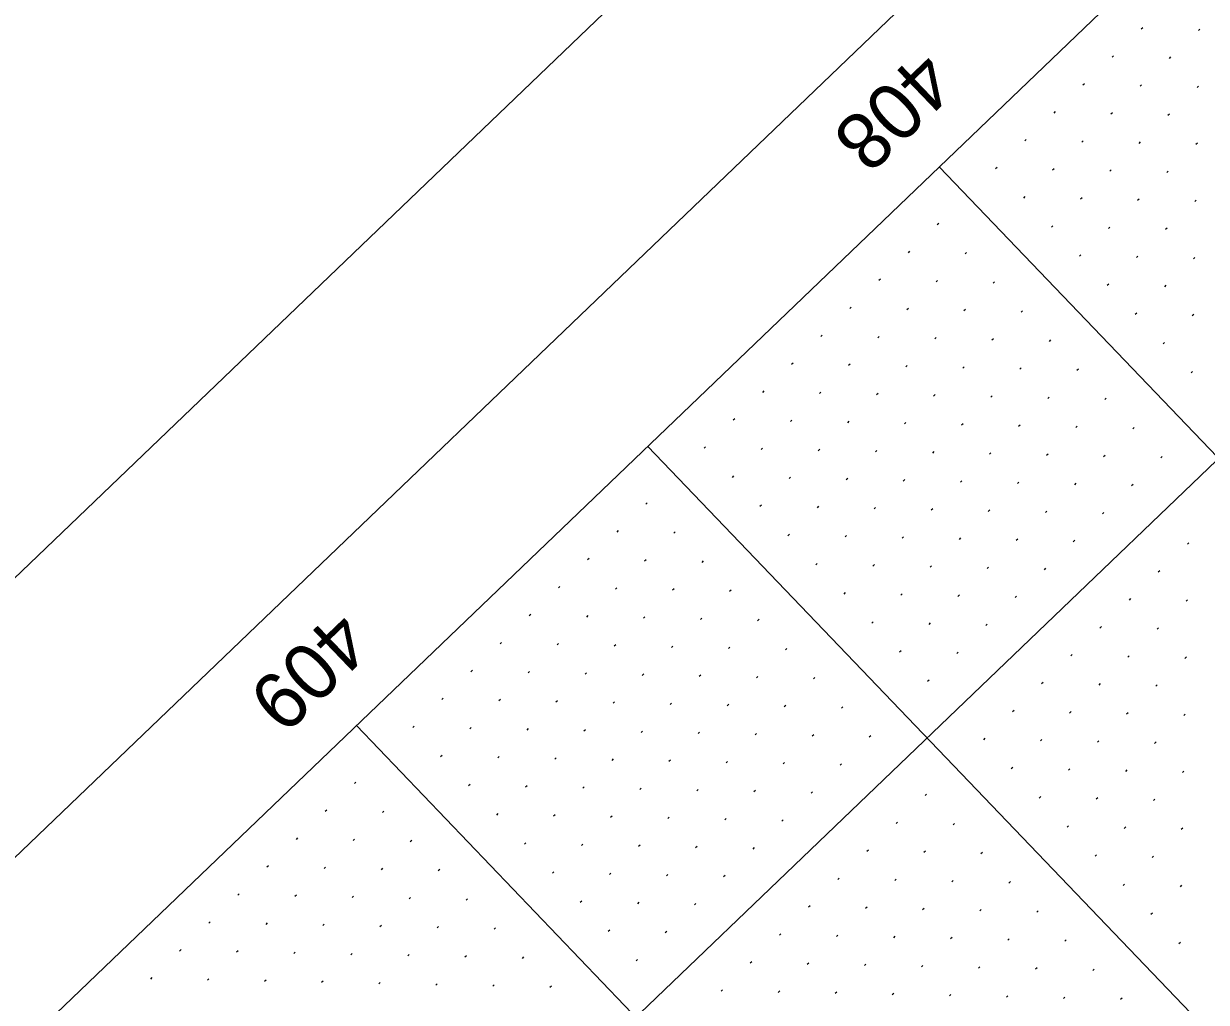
# Model space of a CAD drawing. Extents: x 2148987 to 2151117, y 142806 to 144993.
# Drawn here: x 2149870.3 to 2150016.8, y 144383.4 to 144504.6 of the extents above; entities that cross this region are included whole.
import ezdxf

# ---------------------------------------------------------------- set-up
doc = ezdxf.new("R2010")
doc.units = 0
for name, color, linetype in [('BASELINE', 7, 'Continuous'), ('PR_PIER_PH3', 7, 'Continuous'), ('PR_Road_Concrete', 7, 'Continuous'), ('SHT_Profile_Grid_Minor', 7, 'Continuous'), ('Wall D Bore Txt', 7, 'Continuous')]:
    doc.layers.add(name, color=color, linetype=linetype)

msp = doc.modelspace()

# ---------------------------------------------------------------- linework, layer by layer
at = {"layer": 'BASELINE'}
msp.add_lwpolyline([(2151029.45, 144024.32), (2149802.07, 142848.08), (2149040.98, 143642.27), (2150268.36, 144818.51)], close=True, dxfattribs=at)
at = {"layer": 'PR_PIER_PH3'}
for p, q in [((2150261.97, 144684.26), (2149124.83, 143594.52)), ((2149983.7, 144486.85), (2150329.49, 144126.02)), ((2149947.6, 144452.25), (2150293.55, 144091.26)), ((2149911.5, 144417.66), (2150233.24, 144081.93))]:
    msp.add_line(p, q, dxfattribs=at)
at = {"layer": 'PR_Road_Concrete'}
msp.add_line((2150227.37, 144720.36), (2149279.76, 143812.24), dxfattribs=at)
msp.add_lwpolyline([(2150941.76, 143974.91), (2149804.63, 142885.16), (2149078.13, 143643.25), (2150215.26, 144733)], close=True, dxfattribs=at)
at = {"layer": 'SHT_Profile_Grid_Minor'}
for p, q in [((2150008.91, 144504.08), (2150008.73, 144503.91)), ((2150015.98, 144503.93), (2150015.8, 144503.76)), ((2150005.3, 144500.62), (2150005.12, 144500.45)), ((2150012.37, 144500.47), (2150012.19, 144500.3)), ((2150001.69, 144497.16), (2150001.51, 144496.99)), ((2150008.76, 144497.01), (2150008.58, 144496.84)), ((2150015.83, 144496.86), (2150015.65, 144496.69)), ((2149998.08, 144493.7), (2149997.9, 144493.53)), ((2150005.15, 144493.55), (2150004.97, 144493.38)), ((2150012.22, 144493.4), (2150012.04, 144493.23)), ((2149994.47, 144490.24), (2149994.29, 144490.07)), ((2150001.54, 144490.09), (2150001.36, 144489.92)), ((2150008.61, 144489.94), (2150008.43, 144489.77)), ((2150015.68, 144489.79), (2150015.5, 144489.62)), ((2149990.86, 144486.78), (2149990.68, 144486.61)), ((2149997.93, 144486.63), (2149997.75, 144486.46)), ((2150005, 144486.48), (2150004.82, 144486.31)), ((2150012.07, 144486.33), (2150011.89, 144486.16)), ((2149994.32, 144483.17), (2149994.14, 144483)), ((2150001.39, 144483.02), (2150001.21, 144482.85)), ((2150008.46, 144482.87), (2150008.28, 144482.7)), ((2150015.53, 144482.72), (2150015.35, 144482.55)), ((2149983.64, 144479.86), (2149983.46, 144479.69)), ((2149997.78, 144479.56), (2149997.6, 144479.39)), ((2150004.85, 144479.41), (2150004.67, 144479.24)), ((2150011.92, 144479.26), (2150011.74, 144479.09)), ((2149980.03, 144476.4), (2149979.85, 144476.23)), ((2149987.1, 144476.25), (2149986.92, 144476.08)), ((2150001.24, 144475.95), (2150001.06, 144475.78)), ((2150008.31, 144475.8), (2150008.13, 144475.63)), ((2150015.38, 144475.65), (2150015.2, 144475.48)), ((2149976.42, 144472.94), (2149976.24, 144472.77)), ((2149983.49, 144472.79), (2149983.31, 144472.62)), ((2149990.56, 144472.64), (2149990.38, 144472.47)), ((2150004.7, 144472.34), (2150004.52, 144472.17)), ((2150011.77, 144472.19), (2150011.59, 144472.02)), ((2149972.81, 144469.48), (2149972.63, 144469.31)), ((2149979.88, 144469.33), (2149979.7, 144469.16)), ((2149986.95, 144469.18), (2149986.77, 144469.01)), ((2149994.02, 144469.03), (2149993.84, 144468.86)), ((2150008.16, 144468.73), (2150007.98, 144468.56)), ((2150015.23, 144468.58), (2150015.05, 144468.41)), ((2149969.2, 144466.03), (2149969.02, 144465.85)), ((2149976.27, 144465.87), (2149976.09, 144465.7)), ((2149983.34, 144465.72), (2149983.16, 144465.55)), ((2149990.41, 144465.57), (2149990.23, 144465.4)), ((2149997.48, 144465.42), (2149997.3, 144465.25)), ((2150011.62, 144465.12), (2150011.44, 144464.95)), ((2149965.59, 144462.57), (2149965.41, 144462.39)), ((2149972.66, 144462.42), (2149972.48, 144462.24)), ((2149979.73, 144462.27), (2149979.55, 144462.09)), ((2149986.8, 144462.11), (2149986.62, 144461.94)), ((2149993.87, 144461.96), (2149993.69, 144461.79)), ((2150000.94, 144461.81), (2150000.76, 144461.64)), ((2150015.08, 144461.51), (2150014.9, 144461.34)), ((2149961.98, 144459.11), (2149961.8, 144458.93)), ((2149969.05, 144458.96), (2149968.87, 144458.78)), ((2149976.12, 144458.81), (2149975.94, 144458.63)), ((2149983.19, 144458.66), (2149983.01, 144458.48)), ((2149990.26, 144458.5), (2149990.08, 144458.33)), ((2149997.33, 144458.35), (2149997.15, 144458.18)), ((2150004.4, 144458.2), (2150004.22, 144458.03)), ((2149958.37, 144455.65), (2149958.19, 144455.47)), ((2149965.44, 144455.5), (2149965.26, 144455.32)), ((2149972.51, 144455.35), (2149972.33, 144455.17)), ((2149979.58, 144455.2), (2149979.4, 144455.02)), ((2149986.65, 144455.05), (2149986.47, 144454.87)), ((2149993.72, 144454.89), (2149993.54, 144454.72)), ((2150000.79, 144454.74), (2150000.61, 144454.57)), ((2150007.86, 144454.59), (2150007.68, 144454.42)), ((2149954.76, 144452.19), (2149954.58, 144452.01)), ((2149961.83, 144452.04), (2149961.65, 144451.86)), ((2149968.9, 144451.89), (2149968.72, 144451.71)), ((2149975.97, 144451.74), (2149975.79, 144451.56)), ((2149983.04, 144451.59), (2149982.86, 144451.41)), ((2149990.11, 144451.44), (2149989.93, 144451.26)), ((2149997.18, 144451.28), (2149997, 144451.11)), ((2150004.25, 144451.13), (2150004.07, 144450.96)), ((2150011.32, 144450.98), (2150011.14, 144450.81)), ((2149958.22, 144448.58), (2149958.04, 144448.4)), ((2149965.29, 144448.43), (2149965.11, 144448.25)), ((2149972.36, 144448.28), (2149972.18, 144448.1)), ((2149979.43, 144448.13), (2149979.25, 144447.95)), ((2149986.5, 144447.98), (2149986.32, 144447.8)), ((2149993.57, 144447.83), (2149993.39, 144447.65)), ((2150000.64, 144447.67), (2150000.46, 144447.5)), ((2150007.71, 144447.52), (2150007.53, 144447.35)), ((2149947.54, 144445.27), (2149947.36, 144445.1)), ((2149961.68, 144444.97), (2149961.5, 144444.79)), ((2149968.75, 144444.82), (2149968.57, 144444.64)), ((2149975.82, 144444.67), (2149975.64, 144444.49)), ((2149982.89, 144444.52), (2149982.71, 144444.34)), ((2149989.96, 144444.37), (2149989.78, 144444.19)), ((2149997.03, 144444.22), (2149996.85, 144444.04)), ((2150004.1, 144444.06), (2150003.92, 144443.89)), ((2149943.93, 144441.81), (2149943.75, 144441.64)), ((2149951, 144441.66), (2149950.82, 144441.49)), ((2149965.14, 144441.36), (2149964.96, 144441.18)), ((2149972.21, 144441.21), (2149972.03, 144441.03)), ((2149979.28, 144441.06), (2149979.1, 144440.88)), ((2149986.35, 144440.91), (2149986.17, 144440.73)), ((2149993.42, 144440.76), (2149993.24, 144440.58)), ((2150000.49, 144440.61), (2150000.31, 144440.43)), ((2150014.63, 144440.3), (2150014.44, 144440.13)), ((2149940.32, 144438.35), (2149940.14, 144438.18)), ((2149947.39, 144438.2), (2149947.21, 144438.03)), ((2149954.46, 144438.05), (2149954.28, 144437.88)), ((2149968.6, 144437.75), (2149968.42, 144437.57)), ((2149975.67, 144437.6), (2149975.49, 144437.42)), ((2149982.74, 144437.45), (2149982.56, 144437.27)), ((2149989.81, 144437.3), (2149989.63, 144437.12)), ((2149996.88, 144437.15), (2149996.7, 144436.97)), ((2150011.02, 144436.84), (2150010.83, 144436.67)), ((2149936.71, 144434.89), (2149936.53, 144434.72)), ((2149943.78, 144434.74), (2149943.6, 144434.57)), ((2149950.85, 144434.59), (2149950.67, 144434.42)), ((2149957.92, 144434.44), (2149957.74, 144434.27)), ((2149972.06, 144434.14), (2149971.88, 144433.96)), ((2149979.13, 144433.99), (2149978.95, 144433.81)), ((2149986.2, 144433.84), (2149986.02, 144433.66)), ((2149993.27, 144433.69), (2149993.09, 144433.51)), ((2150007.41, 144433.39), (2150007.22, 144433.21)), ((2150014.47, 144433.23), (2150014.29, 144433.06)), ((2149933.1, 144431.43), (2149932.92, 144431.26)), ((2149940.17, 144431.28), (2149939.99, 144431.11)), ((2149947.24, 144431.13), (2149947.06, 144430.96)), ((2149954.31, 144430.98), (2149954.13, 144430.81)), ((2149961.38, 144430.83), (2149961.2, 144430.66)), ((2149975.52, 144430.53), (2149975.34, 144430.35)), ((2149982.59, 144430.38), (2149982.41, 144430.2)), ((2149989.66, 144430.23), (2149989.48, 144430.05)), ((2150003.8, 144429.93), (2150003.61, 144429.75)), ((2150010.86, 144429.78), (2150010.68, 144429.6)), ((2149929.49, 144427.97), (2149929.31, 144427.8)), ((2149936.56, 144427.82), (2149936.38, 144427.65)), ((2149943.63, 144427.67), (2149943.45, 144427.5)), ((2149950.7, 144427.52), (2149950.52, 144427.35)), ((2149957.77, 144427.37), (2149957.59, 144427.2)), ((2149964.84, 144427.22), (2149964.66, 144427.05)), ((2149978.98, 144426.92), (2149978.8, 144426.74)), ((2149986.05, 144426.77), (2149985.87, 144426.59)), ((2150000.19, 144426.47), (2150000, 144426.29)), ((2150007.25, 144426.32), (2150007.07, 144426.14)), ((2150014.32, 144426.17), (2150014.14, 144425.99)), ((2149925.88, 144424.51), (2149925.7, 144424.34)), ((2149932.95, 144424.36), (2149932.77, 144424.19)), ((2149940.02, 144424.21), (2149939.84, 144424.04)), ((2149947.09, 144424.06), (2149946.91, 144423.89)), ((2149954.16, 144423.91), (2149953.98, 144423.74)), ((2149961.23, 144423.76), (2149961.05, 144423.59)), ((2149968.3, 144423.61), (2149968.12, 144423.44)), ((2149982.44, 144423.31), (2149982.26, 144423.13)), ((2149996.58, 144423.01), (2149996.39, 144422.83)), ((2150003.64, 144422.86), (2150003.46, 144422.68)), ((2150010.71, 144422.71), (2150010.53, 144422.53)), ((2149922.27, 144421.05), (2149922.09, 144420.88)), ((2149929.34, 144420.9), (2149929.16, 144420.73)), ((2149936.41, 144420.75), (2149936.23, 144420.58)), ((2149943.48, 144420.6), (2149943.3, 144420.43)), ((2149950.55, 144420.45), (2149950.37, 144420.28)), ((2149957.62, 144420.3), (2149957.44, 144420.13)), ((2149964.69, 144420.15), (2149964.51, 144419.98)), ((2149971.76, 144420), (2149971.58, 144419.83)), ((2149992.97, 144419.55), (2149992.79, 144419.37)), ((2150000.03, 144419.4), (2149999.85, 144419.22)), ((2150007.1, 144419.25), (2150006.92, 144419.07)), ((2150014.17, 144419.1), (2150013.99, 144418.92)), ((2149918.66, 144417.59), (2149918.48, 144417.42)), ((2149925.73, 144417.44), (2149925.55, 144417.27)), ((2149932.8, 144417.29), (2149932.62, 144417.12)), ((2149939.87, 144417.14), (2149939.69, 144416.97)), ((2149946.94, 144416.99), (2149946.76, 144416.82)), ((2149954.01, 144416.84), (2149953.83, 144416.67)), ((2149961.08, 144416.69), (2149960.9, 144416.52)), ((2149968.15, 144416.54), (2149967.97, 144416.37)), ((2149975.22, 144416.39), (2149975.04, 144416.22)), ((2149989.36, 144416.09), (2149989.18, 144415.91)), ((2149996.43, 144415.94), (2149996.24, 144415.76)), ((2150003.49, 144415.79), (2150003.31, 144415.61)), ((2150010.56, 144415.64), (2150010.38, 144415.46)), ((2149922.12, 144413.98), (2149921.94, 144413.81)), ((2149929.19, 144413.83), (2149929.01, 144413.66)), ((2149936.26, 144413.68), (2149936.08, 144413.51)), ((2149943.33, 144413.53), (2149943.15, 144413.36)), ((2149950.4, 144413.38), (2149950.22, 144413.21)), ((2149957.47, 144413.23), (2149957.29, 144413.06)), ((2149964.54, 144413.08), (2149964.36, 144412.91)), ((2149971.61, 144412.93), (2149971.43, 144412.76)), ((2149992.82, 144412.48), (2149992.63, 144412.3)), ((2149999.88, 144412.33), (2149999.7, 144412.15)), ((2150006.95, 144412.18), (2150006.77, 144412)), ((2149911.44, 144410.67), (2149911.26, 144410.5)), ((2150014.02, 144412.03), (2150013.84, 144411.85)), ((2149925.58, 144410.37), (2149925.4, 144410.2)), ((2149932.65, 144410.22), (2149932.47, 144410.05)), ((2149939.72, 144410.07), (2149939.54, 144409.9)), ((2149946.79, 144409.92), (2149946.61, 144409.75)), ((2149953.86, 144409.77), (2149953.68, 144409.6)), ((2149960.93, 144409.62), (2149960.75, 144409.45)), ((2149968, 144409.47), (2149967.82, 144409.3)), ((2149982.14, 144409.17), (2149981.96, 144409)), ((2149996.27, 144408.87), (2149996.09, 144408.69)), ((2150003.34, 144408.72), (2150003.16, 144408.54)), ((2150010.41, 144408.57), (2150010.23, 144408.39)), ((2149907.83, 144407.21), (2149907.65, 144407.04)), ((2149914.9, 144407.06), (2149914.72, 144406.89)), ((2149929.04, 144406.76), (2149928.86, 144406.59)), ((2149936.11, 144406.61), (2149935.93, 144406.44)), ((2149943.18, 144406.46), (2149943, 144406.29)), ((2149950.25, 144406.31), (2149950.07, 144406.14)), ((2149957.32, 144406.16), (2149957.14, 144405.99)), ((2149964.39, 144406.01), (2149964.21, 144405.84)), ((2149978.53, 144405.71), (2149978.35, 144405.54)), ((2149985.6, 144405.56), (2149985.41, 144405.39)), ((2149999.73, 144405.26), (2149999.55, 144405.09)), ((2150006.8, 144405.11), (2150006.62, 144404.93)), ((2150013.87, 144404.96), (2150013.69, 144404.78)), ((2149904.22, 144403.75), (2149904.04, 144403.58)), ((2149911.29, 144403.6), (2149911.11, 144403.43)), ((2149918.36, 144403.45), (2149918.18, 144403.28)), ((2149932.5, 144403.15), (2149932.32, 144402.98)), ((2149939.57, 144403), (2149939.39, 144402.83)), ((2149946.64, 144402.85), (2149946.46, 144402.68)), ((2149953.71, 144402.7), (2149953.53, 144402.53)), ((2149960.78, 144402.55), (2149960.6, 144402.38)), ((2149974.92, 144402.25), (2149974.74, 144402.08)), ((2149981.99, 144402.1), (2149981.8, 144401.93)), ((2149989.05, 144401.95), (2149988.87, 144401.78)), ((2150003.19, 144401.65), (2150003.01, 144401.48)), ((2150010.26, 144401.5), (2150010.08, 144401.32)), ((2149900.61, 144400.29), (2149900.43, 144400.12)), ((2149907.68, 144400.14), (2149907.5, 144399.97)), ((2149914.75, 144399.99), (2149914.57, 144399.82)), ((2149921.82, 144399.84), (2149921.64, 144399.67)), ((2149935.96, 144399.54), (2149935.78, 144399.37)), ((2149943.03, 144399.39), (2149942.85, 144399.22)), ((2149950.1, 144399.24), (2149949.92, 144399.07)), ((2149957.17, 144399.09), (2149956.99, 144398.92)), ((2149971.31, 144398.79), (2149971.13, 144398.62)), ((2149978.38, 144398.64), (2149978.19, 144398.47)), ((2149985.44, 144398.49), (2149985.26, 144398.32)), ((2149992.51, 144398.34), (2149992.33, 144398.17)), ((2150006.65, 144398.04), (2150006.47, 144397.87)), ((2150013.72, 144397.89), (2150013.54, 144397.71)), ((2149897, 144396.84), (2149896.82, 144396.66)), ((2149904.07, 144396.68), (2149903.89, 144396.51)), ((2149911.14, 144396.53), (2149910.96, 144396.36)), ((2149918.21, 144396.38), (2149918.03, 144396.21)), ((2149925.28, 144396.23), (2149925.1, 144396.06)), ((2149939.42, 144395.93), (2149939.24, 144395.76)), ((2149946.49, 144395.78), (2149946.31, 144395.61)), ((2149953.56, 144395.63), (2149953.38, 144395.46)), ((2149967.7, 144395.33), (2149967.52, 144395.16)), ((2149974.77, 144395.18), (2149974.58, 144395.01)), ((2149981.83, 144395.03), (2149981.65, 144394.86)), ((2149988.9, 144394.88), (2149988.72, 144394.71)), ((2149995.97, 144394.73), (2149995.79, 144394.56)), ((2149893.39, 144393.38), (2149893.21, 144393.2)), ((2149900.46, 144393.23), (2149900.28, 144393.05)), ((2149907.53, 144393.07), (2149907.35, 144392.9)), ((2150010.11, 144394.43), (2150009.93, 144394.26)), ((2149914.6, 144392.92), (2149914.42, 144392.75)), ((2149921.67, 144392.77), (2149921.49, 144392.6)), ((2149928.74, 144392.62), (2149928.56, 144392.45)), ((2149942.88, 144392.32), (2149942.7, 144392.15)), ((2149949.95, 144392.17), (2149949.77, 144392)), ((2149964.09, 144391.87), (2149963.91, 144391.7)), ((2149971.16, 144391.72), (2149970.97, 144391.55)), ((2149978.22, 144391.57), (2149978.04, 144391.4)), ((2149985.29, 144391.42), (2149985.11, 144391.25)), ((2149992.36, 144391.27), (2149992.18, 144391.1)), ((2149999.43, 144391.12), (2149999.25, 144390.95)), ((2150013.57, 144390.82), (2150013.39, 144390.65)), ((2149889.78, 144389.92), (2149889.6, 144389.74)), ((2149896.85, 144389.77), (2149896.67, 144389.59)), ((2149903.92, 144389.62), (2149903.74, 144389.44)), ((2149910.99, 144389.46), (2149910.81, 144389.29)), ((2149918.06, 144389.31), (2149917.88, 144389.14)), ((2149925.13, 144389.16), (2149924.95, 144388.99)), ((2149932.2, 144389.01), (2149932.02, 144388.84)), ((2149946.34, 144388.71), (2149946.16, 144388.54)), ((2149960.48, 144388.41), (2149960.3, 144388.24)), ((2149967.55, 144388.26), (2149967.36, 144388.09)), ((2149974.61, 144388.11), (2149974.43, 144387.94)), ((2149981.68, 144387.96), (2149981.5, 144387.79)), ((2149988.75, 144387.81), (2149988.57, 144387.64)), ((2149995.82, 144387.66), (2149995.64, 144387.49)), ((2150002.89, 144387.51), (2150002.71, 144387.34)), ((2149886.17, 144386.46), (2149885.99, 144386.28)), ((2149893.24, 144386.31), (2149893.06, 144386.13)), ((2149900.31, 144386.16), (2149900.13, 144385.98)), ((2149907.38, 144386.01), (2149907.2, 144385.83)), ((2149914.45, 144385.85), (2149914.27, 144385.68)), ((2149921.52, 144385.7), (2149921.34, 144385.53)), ((2149928.59, 144385.55), (2149928.41, 144385.38)), ((2149935.66, 144385.4), (2149935.48, 144385.23)), ((2149956.87, 144384.95), (2149956.69, 144384.78)), ((2149963.94, 144384.8), (2149963.75, 144384.63)), ((2149971, 144384.65), (2149970.82, 144384.48)), ((2149978.07, 144384.5), (2149977.89, 144384.33)), ((2149985.14, 144384.35), (2149984.96, 144384.18)), ((2149992.21, 144384.2), (2149992.03, 144384.03)), ((2149999.28, 144384.05), (2149999.1, 144383.88)), ((2150006.35, 144383.9), (2150006.17, 144383.73))]:
    msp.add_line(p, q, dxfattribs=at)

# ---------------------------------------------------------------- texts
at = {"layer": 'Wall D Bore Txt'}
for s, p in [('408', (2149981.42, 144501.63)), ('409', (2149909.05, 144432.28))]:
    msp.add_text(s, height=7, rotation=223.7809, dxfattribs=at).set_placement(p)

doc.saveas('drawing.dxf')
